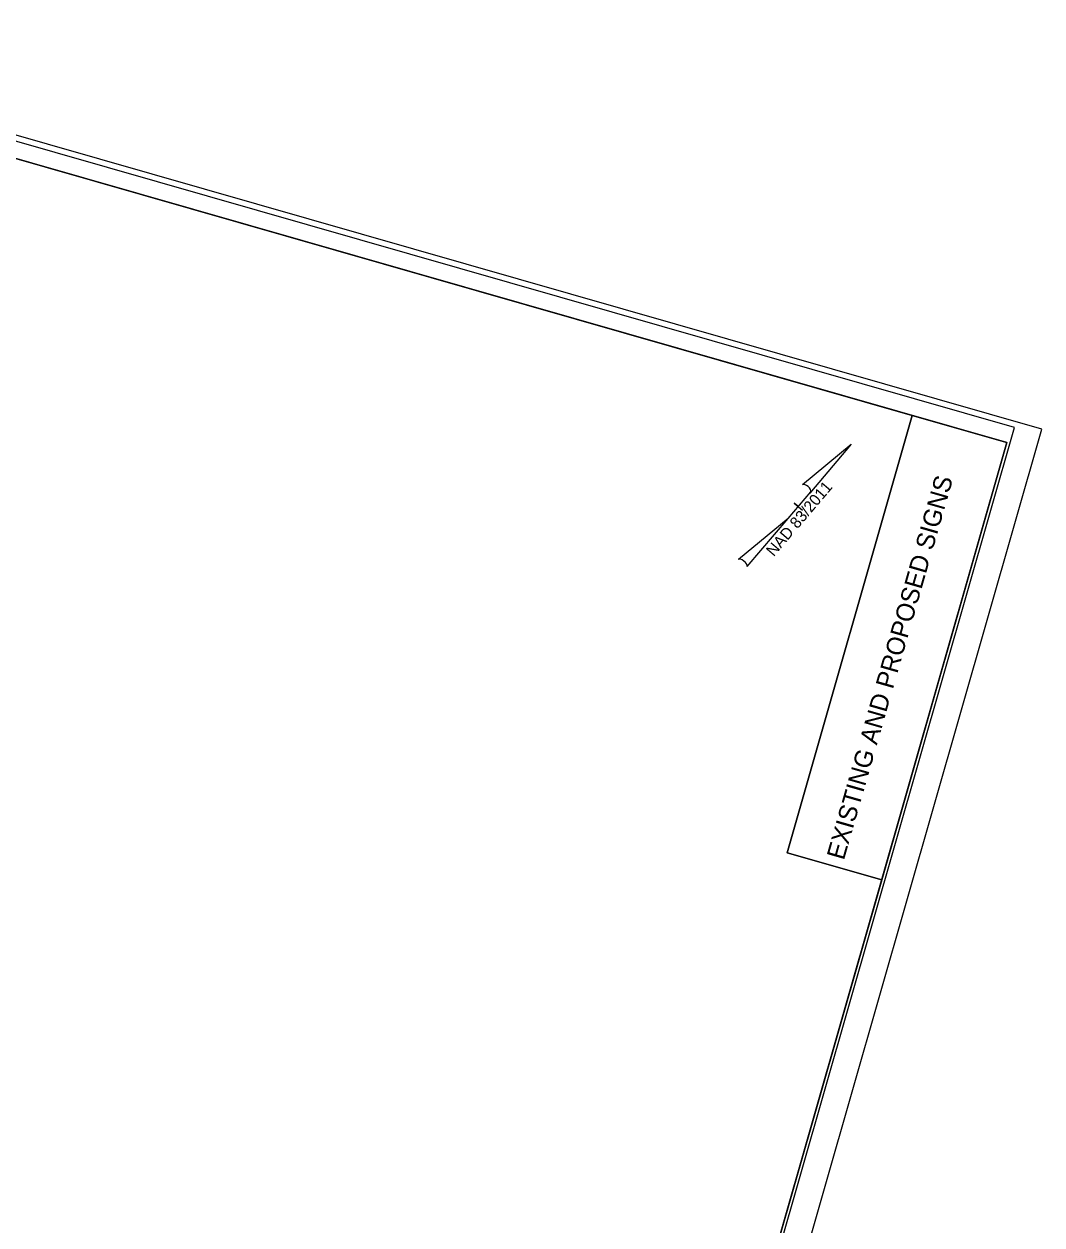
# Model space of a CAD drawing. Extents: x 2096093 to 2098911, y 683546 to 689764.
# Drawn here: x 2097748 to 2098506, y 688738 to 689632 of the extents above; entities that cross this region are included whole.
import ezdxf

# ---------------------------------------------------------------- set-up
doc = ezdxf.new("R2010")
doc.units = 0
for name, color, linetype in [('Default', 7, 'Continuous'), ('Old_Level_10', 7, 'Continuous'), ('Scratch_Level_3', 7, 'Continuous'), ('Scratch_Level_5', 7, 'Continuous'), ('Sheet Plan CELL', 7, 'Continuous'), ('Sheet Plot Border Inside CELL', 7, 'Continuous'), ('Sheet Plot Border Outside CELL', 7, 'Continuous')]:
    doc.layers.add(name, color=color, linetype=linetype)

msp = doc.modelspace()

# ---------------------------------------------------------------- linework, layer by layer
at = {"layer": 'Default'}
for p, q in [((2098328.05, 689288.89), (2098364.35, 689318.84)), ((2098364.39, 689318.81), (2098333.39, 689282.43)), ((2098364.39, 689318.81), (2098364.35, 689318.84)), ((2098364.39, 689318.81), (2098364.35, 689318.84)), ((2098317.3, 689263.56), (2098334.3, 689283.5)), ((2098333.39, 689282.43), (2098334.26, 689283.46)), ((2098321.78, 689274.98), (2098321.74, 689275.01)), ((2098324.48, 689272.68), (2098321.78, 689274.98)), ((2098321.82, 689274.95), (2098327.91, 689269.76)), ((2098317.3, 689263.56), (2098280.3, 689233.01)), ((2098286.82, 689227.71), (2098317.3, 689263.56))]:
    msp.add_line(p, q, dxfattribs=at)
for centre, start_param, end_param in [((2098330.88, 689285.83), 0.216388, 2.908219), ((2098283.42, 689230.14), 0.201328, 3.141593)]:
    msp.add_ellipse(centre, major_axis=(3.2, -2.77), ratio=0.461098, start_param=start_param, end_param=end_param, dxfattribs=at)
at = {"layer": 'Old_Level_10'}
for p, q in [((2098316.63, 689014.71), (2098409.79, 689340.16)), ((2098409.79, 689340.16), (2098480.22, 689319.99)), ((2098480.22, 689319.99), (2098387.02, 688994.56)), ((2098387.02, 688994.56), (2098316.63, 689014.71))]:
    msp.add_line(p, q, dxfattribs=at)
at = {"layer": 'Scratch_Level_3'}
msp.add_line((2098386.42, 688994.73), (2098386.65, 688994.66), dxfattribs=at)
at = {"layer": 'Scratch_Level_5'}
msp.add_lwpolyline([(2098117.81, 688054.49), (2097347.73, 688084.03), (2097057.83, 688167.01), (2097419.22, 689429.54), (2097641.13, 689365.99), (2097692.54, 689545.54), (2098409.79, 689340.16), (2098316.63, 689014.71), (2098387.02, 688994.56)], close=True, dxfattribs=at)
at = {"layer": 'Sheet Plan CELL'}
msp.add_lwpolyline([(2097470.8, 689609.08), (2097057.86, 688167.12), (2098067.29, 687878.05), (2098480.22, 689319.99)], close=True, dxfattribs=at)
at = {"layer": 'Sheet Plot Border Inside CELL'}
msp.add_lwpolyline([(2098027.26, 687729.7), (2098485.9, 689331.31), (2097471.68, 689621.77), (2097013.02, 688020.15)], close=True, dxfattribs=at)
msp.add_lwpolyline([(2098027.26, 687729.7), (2098485.9, 689331.31), (2097471.68, 689621.77), (2097013.02, 688020.15)], close=True, dxfattribs=at)
at = {"layer": 'Sheet Plot Border Outside CELL'}
msp.add_lwpolyline([(2098042.9, 687711.7), (2098506.38, 689330.14), (2097453.69, 689631.6), (2096990.22, 688013.15)], close=True, dxfattribs=at)
msp.add_lwpolyline([(2098042.9, 687711.7), (2098506.38, 689330.14), (2097453.69, 689631.6), (2096990.22, 688013.15)], close=True, dxfattribs=at)

# ---------------------------------------------------------------- texts
at = {"layer": 'Default'}
for s, height, rotation, p in [('EXISTING AND PROPOSED SIGNS', 13.5, 74.01987, (2098358.8, 689008.68)), ('NAD 83/2011', 8.5, 49.56189, (2098306.58, 689234.76))]:
    msp.add_text(s, height=height, rotation=rotation, dxfattribs=at).set_placement(p)

doc.saveas('drawing.dxf')
